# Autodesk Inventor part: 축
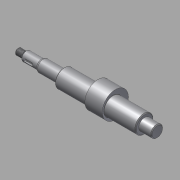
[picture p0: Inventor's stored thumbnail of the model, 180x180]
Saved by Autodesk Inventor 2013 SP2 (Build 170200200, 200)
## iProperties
Created: 2015-12
Part Number: 축
Document SubType Name: Modeling
Designer: mdu
Density: 1 g/cm^3
Material: 일반
Author: mdu
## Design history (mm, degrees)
sketch "스케치1"
  geometry: L1 (62, 100.9)-(62, 67.1) reference; L2 (51, 101.2)-(51, 84) reference; L3 (-51, 84)-(-51, 101.2) reference; L4 (-62, 67.1)-(-62, 100.9) reference; L5 (-51.6, 91.5)-(-61.4, 91.5) reference; L6 (51.6, 91.5)-(61.4, 91.5) reference; L7 (67, 84)-(-109, 84); L8 (-77, 64.201)-(-77, 103.799) reference; L9 (67, 84)-(67, 91.5); L10 (67, 91.5)-(51, 91.5); L11 (51, 91.5)-(51, 95.5); L12 (51, 95.5)-(-51, 95.5); L13 (-51, 95.5)-(-51, 91.5); L14 (-51, 91.5)-(-79, 91.5); L15 (-79, 91.5)-(-79, 90); L16 (-79, 90)-(-99, 90); L17 (-99, 90)-(-99, 87); L18 (-100.5, 88)-(-109, 88); L19 (-109, 88)-(-109, 84); L20 (-99, 87)-(-100.5, 87); L21 (-100.5, 87)-(-100.5, 88); 2 further points
  constraints: 32 end point, 7 parallel, 6 point on line, 5 perpendicular, 2 collinear, 2 horizontal, 1 midpoint, 4 other
  dimensions: "d0" = 5 distance from line of L7.start L1; "d2" = 2 distance between parallel lines of L15 L8; "d3" = 23 diameter of L12 L7; "d4" = 12 diameter of L16 L7; "d5" = 1.5 distance of L17.end L20.end; "d6" = 6 diameter of L20 L7; "d7" = 20 distance of L15.end L16.end; "d8" = 10 distance between parallel lines of L17 L19; "d9" = 8 diameter of L18 L7
revolve "회전1" sketch "스케치1" stored, may be unused: angle "d10" = 90 deg
sketch "스케치2"
  geometry: C1 r 11.5 at (84, 0) reference; C2 r 11.5 at (84, 0) reference; C3 r 16.5 at (87, 0); 1 further point
  constraints: 1 centre point, 1 horizontal alignment
  dimensions: "d11" = 33 diameter of C3; "d12" = 3 distance of C3.centre C1.centre
extrude "돌출1" join sketch "스케치2" stored distance "d13" = 22; taper "d14" = 0 deg
chamfer "모따기1" distance "d15" = 1; stored, may be unused: second distance "d16" = 2, angle "d17" = 45 deg
feature "스레드1" dims "d18" = 10, "d19" = 0
node "작업 평면1"
sketch "스케치3"
  geometry: L1 (-5, -2)-(3, -2); L2 (3, 2)-(-5, 2); L3 (-10, -5)-(-10, 5) reference; A1 r 2 centre (3, 0) between (3, -2) and (3, 2); A2 r 2 centre (-5, 0) between (-5, 2) and (-5, -2); 2 further points
  constraints: 4 end point, 4 point on circle, 4 tangent, 2 centre point, 1 horizontal, 1 horizontal alignment, 1 midpoint, 1 parallel
  dimensions: "d20" = 4 distance between parallel lines of L1 L2; "d21" = 12 dimension on A1 A2; "d22" = 3 distance edge to line of A2 L3
extrude "돌출2" cut sketch "스케치3" distance "d23" = 2.5; taper "d24" = 0 deg
fillet "모깎기1" dims "d25" = 0.3
fillet "모깎기2" dims "d26" = 3
node "솔리드1"
node "참조1"
node "참조2"
node "참조3"
node "참조4"
node "참조5"
node "투영된 루프1"
